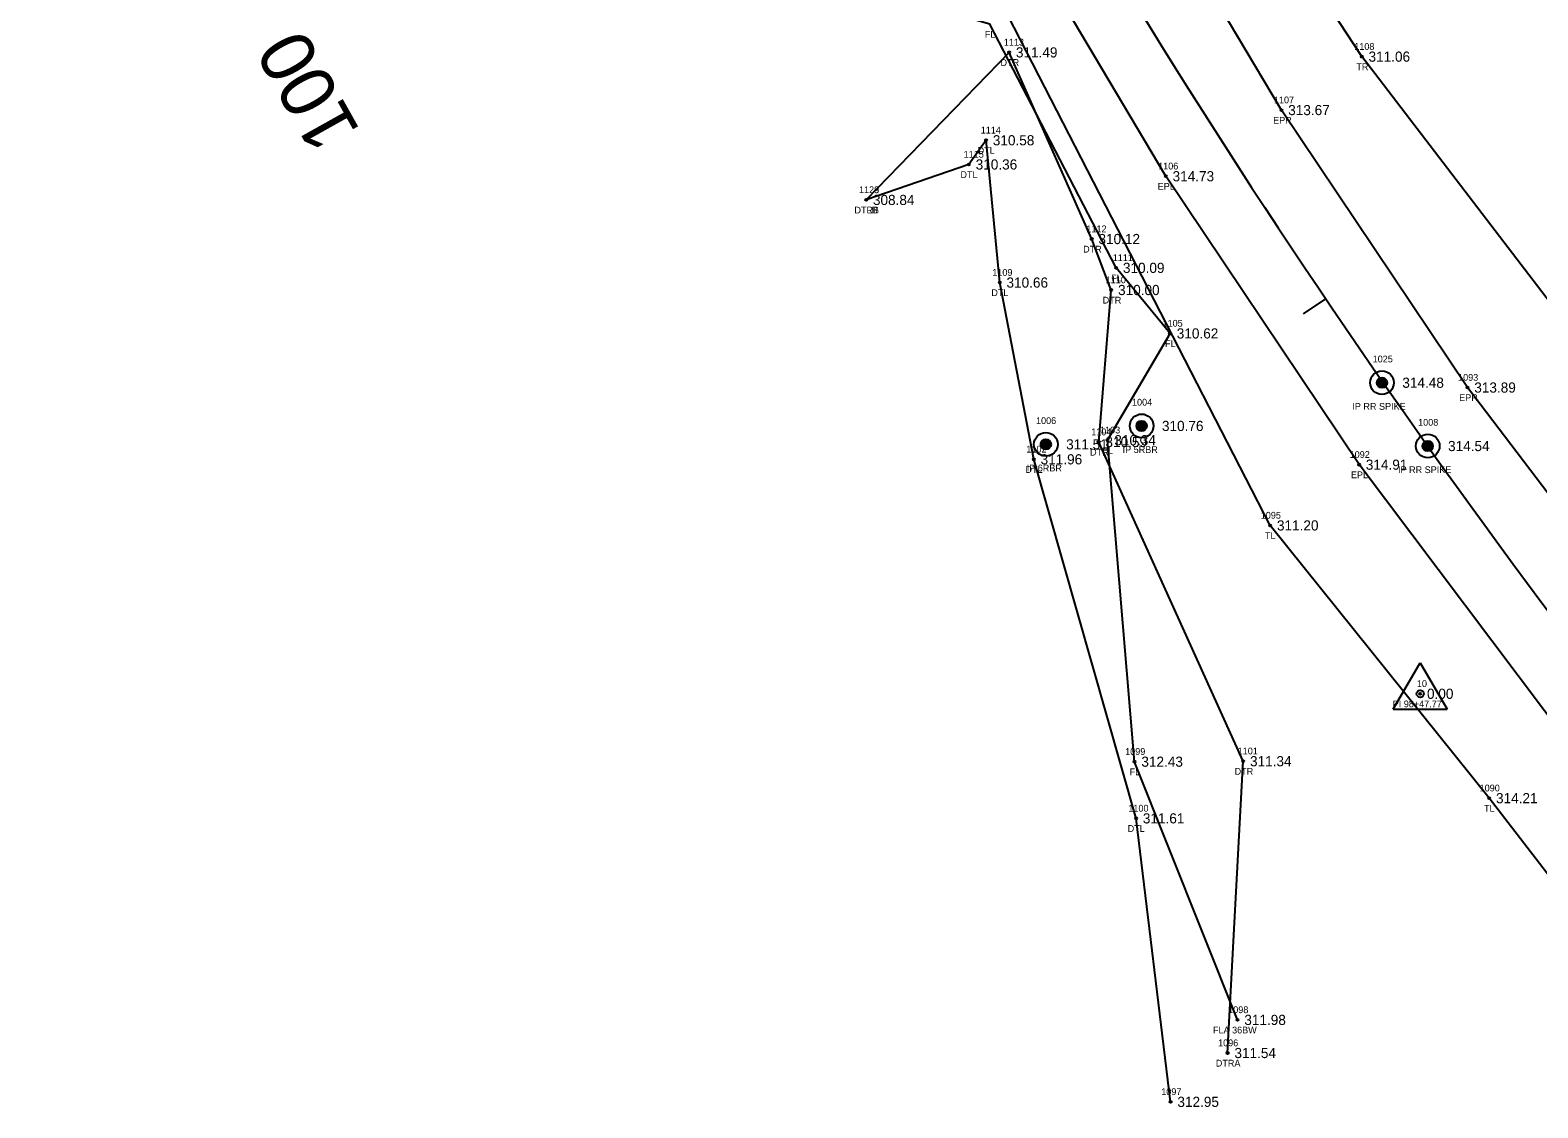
# Model space of a CAD drawing. Extents: x 1865045 to 1867370, y 910391 to 914218.
# Drawn here: x 1866397.5 to 1866620.1, y 910563.9 to 910723.1 of the extents above; entities that cross this region are included whole.
import ezdxf

# ---------------------------------------------------------------- set-up
doc = ezdxf.new("R2010")
doc.units = 0
for name, color, linetype in [('RD_EX_DV_Prop_txCode', 7, 'Continuous'), ('RD_EX_DV_PropPin', 7, 'Continuous'), ('RD_EX_Fence_Other', 7, 'Continuous'), ('RD_EX_Fence_Other_txCode', 7, 'Continuous'), ('RD_EX_H2O', 7, 'Continuous'), ('RD_EX_H2O_txCode', 7, 'Continuous'), ('RD_EX_Road', 7, 'Continuous'), ('RD_EX_Road_txCode', 7, 'Continuous'), ('RD_EX_TX_DV_Prop_ELEV', 7, 'Continuous'), ('RD_EX_TX_Fence_Other_ELEV', 7, 'Continuous'), ('RD_EX_TX_H2O_ELEV', 7, 'Continuous'), ('RD_EX_TX_Road_ELEV', 7, 'Continuous'), ('RD_EX_TX_VEG_ELEV', 7, 'Continuous'), ('RD_EX_VEG', 7, 'Continuous'), ('RD_EX_VEG_txCode', 7, 'Continuous'), ('RD_HC_Cl', 7, 'Continuous'), ('RD_HC_Data', 7, 'Continuous'), ('RD_HC_Data_Tic', 7, 'Continuous'), ('RD_HC_Survey_ELEV', 7, 'Continuous'), ('RD_HC_TX_Sta50', 7, 'Continuous'), ('RD_HC_txCode', 7, 'Continuous'), ('RD_SMD_Locator', 7, 'Continuous')]:
    doc.layers.add(name, color=color, linetype=linetype)

msp = doc.modelspace()

# ---------------------------------------------------------------- linework, layer by layer
at = {"layer": 'RD_EX_DV_PropPin'}
for p, q in [((1866596.8, 910670.29), (1866596.8, 910671.7)), ((1866596.84, 910670.27), (1866596.84, 910671.71)), ((1866596.87, 910670.26), (1866596.87, 910671.72)), ((1866596.91, 910670.25), (1866596.91, 910671.73)), ((1866596.94, 910670.25), (1866596.94, 910671.74)), ((1866596.98, 910670.24), (1866596.98, 910671.75)), ((1866597.01, 910670.24), (1866597.01, 910671.75)), ((1866597.05, 910670.23), (1866597.05, 910671.75)), ((1866597.08, 910670.23), (1866597.08, 910671.75)), ((1866597.12, 910670.23), (1866597.12, 910671.75)), ((1866597.15, 910670.24), (1866597.15, 910671.75)), ((1866597.19, 910670.24), (1866597.19, 910671.75)), ((1866597.22, 910670.25), (1866597.22, 910671.74)), ((1866597.26, 910670.25), (1866597.26, 910671.73)), ((1866597.29, 910670.26), (1866597.29, 910671.72)), ((1866597.33, 910670.27), (1866597.33, 910671.71)), ((1866597.36, 910670.29), (1866597.36, 910671.7)), ((1866596.35, 910670.8), (1866596.35, 910671.19)), ((1866596.38, 910670.7), (1866596.38, 910671.29)), ((1866596.42, 910670.62), (1866596.42, 910671.36)), ((1866596.45, 910670.57), (1866596.45, 910671.42)), ((1866596.49, 910670.52), (1866596.49, 910671.47)), ((1866596.52, 910670.48), (1866596.52, 910671.51)), ((1866596.56, 910670.44), (1866596.56, 910671.54)), ((1866596.59, 910670.41), (1866596.59, 910671.58)), ((1866596.63, 910670.38), (1866596.63, 910671.6)), ((1866596.66, 910670.36), (1866596.66, 910671.63)), ((1866596.7, 910670.34), (1866596.7, 910671.65)), ((1866596.73, 910670.32), (1866596.73, 910671.67)), ((1866596.77, 910670.3), (1866596.77, 910671.69)), ((1866597.4, 910670.3), (1866597.4, 910671.69)), ((1866597.43, 910670.32), (1866597.43, 910671.67)), ((1866597.47, 910670.34), (1866597.47, 910671.65)), ((1866597.5, 910670.36), (1866597.5, 910671.63)), ((1866597.54, 910670.38), (1866597.54, 910671.6)), ((1866597.57, 910670.41), (1866597.57, 910671.58)), ((1866597.61, 910670.44), (1866597.61, 910671.54)), ((1866597.65, 910670.48), (1866597.65, 910671.51)), ((1866597.68, 910670.52), (1866597.68, 910671.47)), ((1866597.72, 910670.57), (1866597.72, 910671.42)), ((1866597.75, 910670.62), (1866597.75, 910671.36)), ((1866597.79, 910670.7), (1866597.79, 910671.29)), ((1866597.82, 910670.8), (1866597.82, 910671.19)), ((1866560.96, 910664.18), (1866560.96, 910665.03)), ((1866561, 910664.13), (1866561, 910665.08)), ((1866561.03, 910664.09), (1866561.03, 910665.12)), ((1866561.07, 910664.06), (1866561.07, 910665.16)), ((1866561.1, 910664.02), (1866561.1, 910665.19)), ((1866561.14, 910664), (1866561.14, 910665.22)), ((1866561.17, 910663.97), (1866561.17, 910665.24)), ((1866561.21, 910663.95), (1866561.21, 910665.26)), ((1866561.24, 910663.93), (1866561.24, 910665.28)), ((1866561.28, 910663.91), (1866561.28, 910665.3)), ((1866561.31, 910663.9), (1866561.31, 910665.31)), ((1866561.35, 910663.89), (1866561.35, 910665.33)), ((1866561.38, 910663.87), (1866561.38, 910665.34)), ((1866561.42, 910663.87), (1866561.42, 910665.35)), ((1866561.45, 910663.86), (1866561.45, 910665.35)), ((1866561.49, 910663.85), (1866561.49, 910665.36)), ((1866561.52, 910663.85), (1866561.52, 910665.36)), ((1866561.56, 910663.85), (1866561.56, 910665.37)), ((1866561.59, 910663.84), (1866561.59, 910665.37)), ((1866561.63, 910663.85), (1866561.63, 910665.37)), ((1866561.66, 910663.85), (1866561.66, 910665.36)), ((1866561.7, 910663.85), (1866561.7, 910665.36)), ((1866561.73, 910663.86), (1866561.73, 910665.35)), ((1866561.77, 910663.87), (1866561.77, 910665.35)), ((1866561.8, 910663.87), (1866561.8, 910665.34)), ((1866561.84, 910663.89), (1866561.84, 910665.33)), ((1866561.87, 910663.9), (1866561.87, 910665.31)), ((1866561.91, 910663.91), (1866561.91, 910665.3)), ((1866561.94, 910663.93), (1866561.94, 910665.28)), ((1866561.98, 910663.95), (1866561.98, 910665.26)), ((1866562.01, 910663.97), (1866562.01, 910665.24)), ((1866562.05, 910664), (1866562.05, 910665.22)), ((1866562.08, 910664.02), (1866562.08, 910665.19)), ((1866562.12, 910664.06), (1866562.12, 910665.16)), ((1866562.15, 910664.09), (1866562.15, 910665.12)), ((1866562.19, 910664.13), (1866562.19, 910665.08)), ((1866562.22, 910664.18), (1866562.22, 910665.03)), ((1866560.86, 910664.41), (1866560.86, 910664.8)), ((1866560.89, 910664.31), (1866560.89, 910664.9)), ((1866560.93, 910664.24), (1866560.93, 910664.98)), ((1866562.26, 910664.24), (1866562.26, 910664.98)), ((1866562.29, 910664.31), (1866562.29, 910664.9)), ((1866562.33, 910664.41), (1866562.33, 910664.8)), ((1866546.72, 910661.7), (1866546.72, 910662.09)), ((1866546.75, 910661.59), (1866546.75, 910662.19)), ((1866546.79, 910661.52), (1866546.79, 910662.26)), ((1866546.82, 910661.46), (1866546.82, 910662.32)), ((1866546.86, 910661.42), (1866546.86, 910662.37)), ((1866546.89, 910661.38), (1866546.89, 910662.41)), ((1866546.93, 910661.34), (1866546.93, 910662.44)), ((1866546.96, 910661.31), (1866546.96, 910662.47)), ((1866547, 910661.28), (1866547, 910662.5)), ((1866547.03, 910661.26), (1866547.03, 910662.53)), ((1866547.07, 910661.24), (1866547.07, 910662.55)), ((1866547.1, 910661.22), (1866547.1, 910662.57)), ((1866547.14, 910661.2), (1866547.14, 910662.58)), ((1866547.17, 910661.18), (1866547.17, 910662.6)), ((1866547.21, 910661.17), (1866547.21, 910662.61)), ((1866547.24, 910661.16), (1866547.24, 910662.62)), ((1866547.28, 910661.15), (1866547.28, 910662.63)), ((1866547.31, 910661.14), (1866547.31, 910662.64)), ((1866547.35, 910661.14), (1866547.35, 910662.65)), ((1866547.38, 910661.13), (1866547.38, 910662.65)), ((1866547.42, 910661.13), (1866547.42, 910662.65)), ((1866547.45, 910661.13), (1866547.45, 910662.65)), ((1866547.49, 910661.13), (1866547.49, 910662.65)), ((1866547.52, 910661.13), (1866547.52, 910662.65)), ((1866547.56, 910661.14), (1866547.56, 910662.65)), ((1866547.59, 910661.14), (1866547.59, 910662.64)), ((1866547.63, 910661.15), (1866547.63, 910662.63)), ((1866547.66, 910661.16), (1866547.66, 910662.62)), ((1866547.7, 910661.17), (1866547.7, 910662.61)), ((1866547.73, 910661.18), (1866547.73, 910662.6)), ((1866547.77, 910661.2), (1866547.77, 910662.58)), ((1866547.8, 910661.22), (1866547.8, 910662.57)), ((1866547.84, 910661.24), (1866547.84, 910662.55)), ((1866547.87, 910661.26), (1866547.87, 910662.53)), ((1866547.91, 910661.28), (1866547.91, 910662.5)), ((1866547.94, 910661.31), (1866547.94, 910662.47)), ((1866547.98, 910661.34), (1866547.98, 910662.44)), ((1866548.01, 910661.38), (1866548.01, 910662.41)), ((1866548.05, 910661.42), (1866548.05, 910662.37)), ((1866548.08, 910661.46), (1866548.08, 910662.32)), ((1866548.12, 910661.52), (1866548.12, 910662.26)), ((1866548.15, 910661.59), (1866548.15, 910662.19)), ((1866548.19, 910661.7), (1866548.19, 910662.09)), ((1866603.1, 910661.45), (1866603.1, 910661.84)), ((1866603.13, 910661.35), (1866603.13, 910661.94)), ((1866603.17, 910661.27), (1866603.17, 910662.01)), ((1866603.2, 910661.22), (1866603.2, 910662.07)), ((1866603.24, 910661.17), (1866603.24, 910662.12)), ((1866603.27, 910661.13), (1866603.27, 910662.16)), ((1866603.31, 910661.09), (1866603.31, 910662.2)), ((1866603.34, 910661.06), (1866603.34, 910662.23)), ((1866603.38, 910661.03), (1866603.38, 910662.25)), ((1866603.41, 910661.01), (1866603.41, 910662.28)), ((1866603.45, 910660.99), (1866603.45, 910662.3)), ((1866603.48, 910660.97), (1866603.48, 910662.32)), ((1866603.52, 910660.95), (1866603.52, 910662.34)), ((1866603.55, 910660.94), (1866603.55, 910662.35)), ((1866603.59, 910660.92), (1866603.59, 910662.36)), ((1866603.62, 910660.91), (1866603.62, 910662.38)), ((1866603.66, 910660.9), (1866603.66, 910662.38)), ((1866603.69, 910660.9), (1866603.69, 910662.39)), ((1866603.73, 910660.89), (1866603.73, 910662.4)), ((1866603.76, 910660.89), (1866603.76, 910662.4)), ((1866603.8, 910660.88), (1866603.8, 910662.4)), ((1866603.83, 910660.88), (1866603.83, 910662.41)), ((1866603.87, 910660.88), (1866603.87, 910662.4)), ((1866603.9, 910660.89), (1866603.9, 910662.4)), ((1866603.94, 910660.89), (1866603.94, 910662.4)), ((1866603.97, 910660.9), (1866603.97, 910662.39)), ((1866604.01, 910660.9), (1866604.01, 910662.38)), ((1866604.04, 910660.91), (1866604.04, 910662.38)), ((1866604.08, 910660.92), (1866604.08, 910662.36)), ((1866604.11, 910660.94), (1866604.11, 910662.35)), ((1866604.15, 910660.95), (1866604.15, 910662.34)), ((1866604.18, 910660.97), (1866604.18, 910662.32)), ((1866604.22, 910660.99), (1866604.22, 910662.3)), ((1866604.25, 910661.01), (1866604.25, 910662.28)), ((1866604.29, 910661.03), (1866604.29, 910662.25)), ((1866604.32, 910661.06), (1866604.32, 910662.23)), ((1866604.36, 910661.09), (1866604.36, 910662.2)), ((1866604.39, 910661.13), (1866604.39, 910662.16)), ((1866604.43, 910661.17), (1866604.43, 910662.12)), ((1866604.46, 910661.22), (1866604.46, 910662.07)), ((1866604.5, 910661.27), (1866604.5, 910662.01)), ((1866604.53, 910661.35), (1866604.53, 910661.94)), ((1866604.57, 910661.45), (1866604.57, 910661.84))]:
    msp.add_line(p, q, dxfattribs=at)
for centre, radius in [((1866597.08, 910670.99), 1.75), ((1866597.08, 910670.99), 0.761), ((1866561.59, 910664.61), 1.75), ((1866561.59, 910664.61), 0.761), ((1866547.45, 910661.89), 1.75), ((1866603.83, 910661.64), 1.75), ((1866547.45, 910661.89), 0.761), ((1866603.83, 910661.64), 0.761)]:
    msp.add_circle(centre, radius, dxfattribs=at)
at = {"layer": 'RD_EX_Fence_Other'}
msp.add_lwpolyline([(1866575.75, 910576.9), (1866560.55, 910615.03), (1866556.56, 910662.5), (1866565.78, 910678.27), (1866557.83, 910687.95), (1866539.18, 910723.94), (1866502.37, 910734.46)], dxfattribs=at)
at = {"layer": 'RD_EX_H2O'}
for points in [[(1866574.29, 910572.01), (1866576.59, 910615.1), (1866555.25, 910662.23), (1866557.11, 910684.68), (1866554.22, 910692.21), (1866542.03, 910719.77), (1866520.92, 910697.98)], [(1866565.87, 910564.8), (1866560.77, 910606.66), (1866545.68, 910659.68), (1866540.64, 910685.78), (1866538.62, 910706.79), (1866536.09, 910703.22), (1866520.92, 910697.98)]]:
    msp.add_lwpolyline(points, dxfattribs=at)
at = {"layer": 'RD_EX_Road'}
for points in [[(1866813.99, 910446.88), (1866778.44, 910479.3), (1866742.34, 910514.45), (1866706.87, 910550.71), (1866695.16, 910564.33), (1866672.6, 910589.75), (1866641.04, 910629.03), (1866609.7, 910670.28), (1866582.23, 910711.25), (1866556.44, 910754.58), (1866532.04, 910798.87), (1866507.56, 910846.03), (1866483.5, 910895.43), (1866461.16, 910941.96), (1866414.86, 911037.95), (1866406.11, 911034.1)], [(1866800.58, 910432.45), (1866764.32, 910465.74), (1866727.39, 910500.95), (1866691.9, 910537.68), (1866657.44, 910577.07), (1866624.97, 910617.36), (1866593.69, 910658.89), (1866565.16, 910701.48), (1866538.98, 910745.57), (1866531.34, 910758.5), (1866513.94, 910791.05), (1866489.48, 910838.44), (1866465.73, 910886.02), (1866443.47, 910933.62), (1866397.5, 911029.82), (1866406.11, 911034.1)]]:
    msp.add_lwpolyline(points, dxfattribs=at)
at = {"layer": 'RD_EX_VEG'}
for points in [[(1866625.81, 910677.72), (1866594.09, 910719.14), (1866566.47, 910761.23), (1866543.27, 910805.65), (1866519.83, 910853.48), (1866496.01, 910901.81), (1866477.92, 910951.04)], [(1866770.74, 910392.93), (1866734.38, 910438.07), (1866709.99, 910485.53), (1866679.02, 910526.15), (1866645.41, 910567.43), (1866612.91, 910609.64), (1866580.57, 910649.92), (1866452.86, 910898.44)]]:
    msp.add_lwpolyline(points, dxfattribs=at)
at = {"layer": 'RD_HC_Cl'}
msp.add_arc((1867567.42, 911345.48), 1181.58, 205.67399, 227.8297, dxfattribs=at)
at = {"layer": 'RD_HC_Data'}
for p, q in [((1866598.75, 910622.76), (1866602.72, 910629.64)), ((1866602.72, 910629.64), (1866606.69, 910622.76)), ((1866598.75, 910622.76), (1866606.69, 910622.76))]:
    msp.add_line(p, q, dxfattribs=at)
msp.add_circle((1866602.72, 910625.06), 0.529, dxfattribs=at)
at = {"layer": 'RD_HC_Data_Tic'}
msp.add_line((1866588.76, 910683.4), (1866585.45, 910681.15), dxfattribs=at)
at = {"layer": 'RD_SMD_Locator'}
for centre in [(1866542.03, 910719.77), (1866594.09, 910719.14), (1866582.23, 910711.25), (1866538.62, 910706.79), (1866536.09, 910703.22), (1866565.16, 910701.48), (1866520.92, 910697.98), (1866520.92, 910697.98), (1866554.22, 910692.21), (1866557.83, 910687.95), (1866540.64, 910685.78), (1866557.11, 910684.68), (1866565.78, 910678.27), (1866597.08, 910670.99), (1866609.7, 910670.28), (1866561.59, 910664.61), (1866547.45, 910661.89), (1866555.25, 910662.23), (1866556.56, 910662.5), (1866603.83, 910661.64), (1866545.68, 910659.68), (1866593.69, 910658.89), (1866580.57, 910649.92), (1866602.72, 910625.06), (1866560.55, 910615.03), (1866576.59, 910615.1), (1866612.91, 910609.64), (1866560.77, 910606.66), (1866575.75, 910576.9), (1866574.29, 910572.01), (1866565.87, 910564.8)]:
    msp.add_circle(centre, 0.15, dxfattribs=at)

# ---------------------------------------------------------------- texts
at = {"layer": 'RD_EX_DV_Prop_txCode'}
for s, p in [('1025', (1866595.7, 910673.99)), ('1004', (1866560.17, 910667.61)), ('IP RR SPIKE', (1866592.7, 910666.99)), ('1006', (1866546, 910664.89)), ('1008', (1866602.41, 910664.64)), ('IP 5RBR', (1866558.78, 910660.61)), ('IP 6RBR', (1866544.62, 910657.89)), ('IP RR SPIKE', (1866599.44, 910657.64))]:
    msp.add_text(s, height=1, dxfattribs=at).set_placement(p)
at = {"layer": 'RD_EX_Fence_Other_txCode'}
for s, p in [('FL', (1866538.45, 910721.94)), ('1111', (1866557.33, 910688.95)), ('FL', (1866557.09, 910685.95)), ('1105', (1866564.68, 910679.27)), ('FL', (1866565.05, 910676.27)), ('1103', (1866555.45, 910663.5)), ('FL', (1866555.82, 910660.5)), ('1099', (1866559.16, 910616.03)), ('FL', (1866559.82, 910613.03)), ('1098', (1866574.37, 910577.9)), ('FLA 36BW', (1866572.12, 910574.9))]:
    msp.add_text(s, height=1, dxfattribs=at).set_placement(p)
at = {"layer": 'RD_EX_H2O_txCode'}
for s, p in [('1113', (1866541.25, 910720.77)), ('DTR', (1866540.76, 910717.77)), ('1114', (1866537.84, 910707.79)), ('1115', (1866535.31, 910704.22)), ('DTL', (1866537.38, 910704.79)), ('DTL', (1866534.84, 910701.22)), ('1128', (1866519.86, 910698.98)), ('1129', (1866519.86, 910698.98)), ('DTRB', (1866519.18, 910695.98)), ('DTLB', (1866519.2, 910695.98)), ('1112', (1866553.44, 910693.21)), ('DTR', (1866552.95, 910690.21)), ('1109', (1866539.54, 910686.78)), ('1110', (1866556.29, 910685.68)), ('DTL', (1866539.4, 910683.78)), ('DTR', (1866555.84, 910682.68)), ('1104', (1866554.15, 910663.23)), ('1102', (1866544.58, 910660.68)), ('DTR', (1866553.98, 910660.23)), ('DTL', (1866544.44, 910657.68)), ('1101', (1866575.77, 910616.1)), ('DTR', (1866575.32, 910613.1)), ('1100', (1866559.63, 910607.66)), ('DTL', (1866559.53, 910604.66)), ('1096', (1866572.88, 910573.01)), ('DTRA', (1866572.54, 910570.01)), ('1097', (1866564.49, 910565.8))]:
    msp.add_text(s, height=1, dxfattribs=at).set_placement(p)
at = {"layer": 'RD_EX_Road_txCode'}
for s, p in [('1107', (1866581.12, 910712.25)), ('EPR', (1866581, 910709.25)), ('1106', (1866564.03, 910702.48)), ('EPL', (1866563.96, 910699.48)), ('1093', (1866608.31, 910671.28)), ('EPR', (1866608.47, 910668.28)), ('1092', (1866592.3, 910659.89)), ('EPL', (1866592.49, 910656.89))]:
    msp.add_text(s, height=1, dxfattribs=at).set_placement(p)
at = {"layer": 'RD_EX_TX_DV_Prop_ELEV'}
for s, p in [('314.48', (1866600.08, 910670.24)), ('310.76', (1866564.59, 910663.86)), ('311.51', (1866550.45, 910661.14)), ('314.54', (1866606.83, 910660.89))]:
    msp.add_text(s, height=1.5, dxfattribs=at).set_placement(p)
at = {"layer": 'RD_EX_TX_Fence_Other_ELEV'}
for s, p in [('310.09', (1866558.83, 910687.2)), ('310.62', (1866566.78, 910677.52)), ('310.34', (1866557.56, 910661.75)), ('312.43', (1866561.55, 910614.28)), ('311.98', (1866576.75, 910576.15))]:
    msp.add_text(s, height=1.5, dxfattribs=at).set_placement(p)
at = {"layer": 'RD_EX_TX_H2O_ELEV'}
for s, p in [('311.49', (1866543.03, 910719.02)), ('310.58', (1866539.62, 910706.04)), ('310.36', (1866537.09, 910702.47)), ('308.84', (1866521.92, 910697.23)), ('308.84', (1866521.92, 910697.23)), ('310.12', (1866555.22, 910691.46)), ('310.66', (1866541.64, 910685.03)), ('310.00', (1866558.11, 910683.93)), ('310.59', (1866556.25, 910661.48)), ('311.96', (1866546.68, 910658.93)), ('311.34', (1866577.59, 910614.35)), ('311.61', (1866561.77, 910605.91)), ('311.54', (1866575.29, 910571.26)), ('312.95', (1866566.87, 910564.05))]:
    msp.add_text(s, height=1.5, dxfattribs=at).set_placement(p)
at = {"layer": 'RD_EX_TX_Road_ELEV'}
for s, p in [('313.67', (1866583.23, 910710.5)), ('314.73', (1866566.16, 910700.73)), ('313.89', (1866610.7, 910669.53)), ('314.91', (1866594.69, 910658.14))]:
    msp.add_text(s, height=1.5, dxfattribs=at).set_placement(p)
at = {"layer": 'RD_EX_TX_VEG_ELEV'}
for s, p in [('311.06', (1866595.09, 910718.39)), ('311.20', (1866581.57, 910649.17)), ('314.21', (1866613.91, 910608.89))]:
    msp.add_text(s, height=1.5, dxfattribs=at).set_placement(p)
at = {"layer": 'RD_EX_VEG_txCode'}
for s, p in [('1108', (1866592.98, 910720.14)), ('TR', (1866593.29, 910717.14)), ('1095', (1866579.18, 910650.92)), ('TL', (1866579.8, 910647.92)), ('1090', (1866611.49, 910610.64)), ('TL', (1866612.14, 910607.64))]:
    msp.add_text(s, height=1, dxfattribs=at).set_placement(p)
at = {"layer": 'RD_HC_Survey_ELEV'}
msp.add_text('0.00', height=1.5, dxfattribs=at).set_placement((1866603.72, 910624.31))
at = {"layer": 'RD_HC_TX_Sta50'}
msp.add_text('100', height=8, rotation=119.2301, dxfattribs=at).set_placement((1866446.31, 910708.13))
at = {"layer": 'RD_HC_txCode'}
for s, p in [('10', (1866602.23, 910626.06)), ('PI 98+47.77', (1866598.66, 910623.06))]:
    msp.add_text(s, height=1, dxfattribs=at).set_placement(p)

doc.saveas('drawing.dxf')
